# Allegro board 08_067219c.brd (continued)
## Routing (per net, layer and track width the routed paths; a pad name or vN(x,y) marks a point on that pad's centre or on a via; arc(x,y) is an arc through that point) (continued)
ADP2360_PG: length 65.4
  TOP w0.203: U8.2 10.47,17.58 v1(9.91,17.02) R29.1 ; R15.1 v1(29.08,58.17)
  BOTTOM w0.203: v1(29.08,58.17) 29.62,58.7 29.62,60.81 28.83,61.59 19.68,61.59 18.54,60.45 18.54,41.91 13.72,37.08 12.95,37.08 12.21,36.34 12.21,24.27 9.4,21.46 9.4,17.53 v1(9.91,17.02)
ADR1/SPISSO: length 72.7
  TOP w0.178: R82.2 v1(66.55,47.68) ; R128.1 R31.2 P14.1 28.05,50.93 33.53,50.93 v1(33.78,51.18) R13.2
  BOTTOM w0.178: v1(66.55,47.68) 66.55,48.51 64.26,50.8 64.26,62.68 62.28,64.66 36.14,64.66 35.56,64.07 35.56,52.07 34.67,51.18 v1(33.78,51.18)
ADR2/IO2/MCLK: length 134.9
  TOP w0.178: P17.1 R34.1 R32.2 ; v1(50.8,111.76) 51.07,112.03 A2.1 ; v1(44.58,84.68) 44.58,84.69 44.24,85.03 U10.32 ; v1(36.07,50.5) 37.13,50.5 37.31,50.32 U7.23
  TOP w0.508: R70.2 v1(47.19,63.94)
  L3_PWR w0.178: P17.1 24.77,49.02 22.99,50.8 20.2,50.8 18.58,52.42 18.58,63.92 37.21,82.55 42.45,82.55 v1(44.58,84.68) 45,85.1 45,88.65 41.55,92.1 41.55,96.8 41.91,97.16 41.91,105.28 48.39,111.76 v1(50.8,111.76)
  BOTTOM w0.178: 36.07,50.5 33.45,50.5 33.02,50.93 28.07,50.93 P17.1 ; 36.07,50.5 v1(36.07,50.5) ; 36.07,50.5 36.07,51.28 35.94,51.4 35.94,62.74 36.77,63.57 45.03,63.57 45.4,63.94 v1(47.19,63.94)
BD28623_BCLK: length 2.5
  TOP w0.178: R119.1 52.07,108.24 51.81,107.98 R127.2
BD28623_MUTEX: length 94.1
  TOP w0.203: A2.7 54.4,113.24 54.69,112.95 54.69,111.81 55.21,111.29 55.21,109.38 56.26,108.33 v1(56.26,108.31) 56.67,108.31 57.15,107.83 R42.2
  BOTTOM w0.203: v1(56.26,108.31) 58.67,105.89 58.67,96.9 57.4,95.63 55.5,95.63 54.48,94.61 39.24,94.61 38.86,94.23 38.86,92.2 39.24,91.82 40.95,91.82 42.89,89.89 44.09,89.89 46,87.99 46,84.36 44.93,83.29 44.93,77.83 41.66,74.55 38.35,74.55 37.34,75.56 30.35,75.56 23.88,69.09 P23.3
BD28623_SDATA_IN: length 79
  TOP w0.178: R11.1 v1(39.76,61.7) ; R118.1 v1(50.93,108.97) ; R75.2 v1(57.35,63.32)
  L3_PWR w0.178: v1(50.93,108.97) 52.07,110.11 56.13,110.11 57.87,108.37 57.87,106.34 58.42,105.79 58.42,98.16 57.4,97.14 57.4,72.01 57.87,71.54 57.87,71.53 58.67,70.73 58.67,64.65 v1(57.35,63.32) 55.77,64.9 49.4,64.9 47.62,63.12 43.81,63.12 43.48,62.79 43.48,62.03 42.8,61.34 41.15,61.34 40.79,61.7 v1(39.76,61.7)
  BOTTOM w0.178: v1(39.76,61.7) 39.77,61.71 C5.2
LT3502_FB: length 3
  TOP w0.203: U2.3 14.32,40.67 15.11,39.89 R2.2
  TOP w0.254: R2.2 14.87,39.52 R3.2
MP1: length 53.4
  TOP w0.203: v1(46.48,76.2) 46.74,76.46 U10.10 ; v1(64.2,70.93) R129.1 U9.1
  BOTTOM w0.203: P5.1 43.05,90.3 44.32,90.3 46.48,88.14 46.48,83.19 48.03,81.64 48.03,79.34 47.15,78.46 47.09,78.46 46.48,77.85 v1(46.48,76.2) 46.48,75.19 48.42,73.25 54.33,73.25 57.43,76.35 64.62,76.35 65.66,75.31 65.66,72.39 v1(64.2,70.93)
MP2: length 8.5
  TOP w0.254: P5.3 44.32,91.57 44.32,90.8 45.74,89.39 U10.29
MP3: length 7.7
  TOP w0.254: U10.28 46.24,89.65 45.22,90.67 P5.5
MP7: length 18.6
  TOP w0.203: v1(51.69,79.76) 50.42,79.76 50.19,79.53 U10.14
  BOTTOM w0.203: v1(51.69,79.76) 52.83,80.9 52.83,88.14 P5.7
MP8: length 8.7
  TOP w0.254: U10.27 46.74,89.65 P5.9
MP9: length 10.5
  TOP w0.254: U10.26 47.24,89.15 49.66,91.57 51.2,91.57 P5.11
PDM_CLK: length 86.8
  TOP w0.178: v1(52.28,63.32) 52.27,63.34 R72.2
  TOP w0.203: R52.2 v1(48.07,27.78)
  L3_PWR w0.178: v1(52.28,63.32) 50.3,61.34 43.69,61.34 43.05,60.71 40.51,60.71 40.07,60.26 37.02,60.26 34.67,57.91 30.48,57.91 29.97,57.4 29.07,57.4 28.81,57.66 P16.2
  BOTTOM w0.178: P16.2 27.56,56.52 26.8,55.75 25.4,55.75 23.62,53.98 23.62,48.77 22.99,48.13 22.99,47.5 23.38,47.1 29.86,47.1 31.37,45.59 31.37,42.43 31.89,41.91 36.96,41.91 37.21,41.66 37.21,40.39 39.12,38.48 40.01,38.48 41.95,36.54 43.4,36.54 45.59,38.73 47.62,38.73 48.89,37.46 48.89,30.35 48.07,29.53 v1(48.07,27.78)
PDM_DATA0: length 65.2
  TOP w0.178: R53.2 v1(40,37.72) ; v1(46.51,26.03) C67.2 45.71,26.03 R56.2
  BOTTOM w0.178: P4.1 21.53,58.93 25.1,58.93 25.27,58.75 25.27,56.77 24.89,56.39 23.49,56.39 21.46,54.36 21.46,46.89 24.03,44.32 27.69,44.32 28.33,44.97 30.09,44.97 30.35,44.7 30.35,41.94 32.28,40 37.05,40 39.34,37.72 v1(40,37.72) 41.66,36.06 41.66,25.65 42.3,25.01 45.49,25.01 v1(46.51,26.03)
PDM_DATA1: length 121.3
  TOP w0.178: v1(59.06,44.58) R54.2 C66.2 ; R74.2 v1(54.81,63.32) ; R55.2 v1(29.71,44.45)
  L3_PWR w0.178: P23.1 23.88,56.07 25.17,54.78 30.01,54.78 31.8,56.57 34.21,56.57 37.07,59.42 42.66,59.42 43.92,60.68 50.77,60.68 53.42,63.32 v1(54.81,63.32)
  BOTTOM w0.178: P23.1 20.95,54.74 20.95,46.74 23.75,43.94 28.07,43.94 28.58,44.45 v1(29.71,44.45) 29.71,41.79 31.88,39.62 36.7,39.62 39.12,37.21 39.75,37.21 41.16,35.8 41.16,25.51 42.05,24.63 47.36,24.63 50.15,27.42 50.53,27.42 50.8,27.69 50.8,31.5 56.77,37.46 56.77,39.12 59.06,41.41 v1(59.06,44.58)
SPI_EEPROM_CS: length 8
  TOP w0.178: R71.2 v1(49.73,63.74)
  TOP w0.508: R8.1 v1(44.07,62.23)
  L3_PWR w0.178: v1(44.07,62.23) 44.45,61.85 47.84,61.85 v1(49.73,63.74)
UNNAMED_2_AD243XW_I5_ACM: length 7.5
  TOP w0.254: U7.27 v1(42.7,49.78)
  BOTTOM w0.508: C86.2 41.91,44.7 41.91,45.97 42.7,46.76 v1(42.7,49.78) C85.2
UNNAMED_2_AD243XW_I5_BCLK: length 26.4
  TOP w0.178: R10.2 41.78,59.05 42.04,58.8 v1(42.67,58.8) 43.39,58.09 43.39,57.35 43.2,57.16 U7.9
  L3_PWR w0.178: v1(42.67,58.8) 43.26,59.39 47.19,59.39 47.65,59.84 52.73,59.84 55.12,62.23 58.67,62.23 59.82,61.09 P11.1
UNNAMED_2_AD243XW_I5_BCM: length 7.5
  TOP w0.254: U7.35 v1(46.7,49.78)
  BOTTOM w0.508: C43.2 47.62,44.58 47.62,45.34 46.33,46.64 C89.2 46.33,49.41 v1(46.7,49.78)
UNNAMED_2_AD243XW_I5_DVDD1: length 24.2
  TOP w0.254: U7.3 46.22,56.03 46.22,56.51 46.33,56.62 v1(46.33,56.92) 46.7,56.55 U7.2
  TOP w0.508: v1(46.33,57.38) v1(46.33,56.92)
  BOTTOM w0.254: R4.1 47,61.56 47.34,61.9 56.38,61.9 56.63,61.65 56.63,60.21 56.91,59.93 60.08,59.93 P9.1
  BOTTOM w0.508: R4.1 47,61.04 46.2,60.24 C2.1 C4.2 46.2,57.51 v1(46.33,57.38) v1(46.33,56.92)
UNNAMED_2_AD243XW_I5_GPIO7: length 12.3
  TOP w0.178: U7.14 38.91,54.82 37.34,56.39 37.34,57.66 36.83,58.17 R15.2
UNNAMED_2_AD243XW_I5_IRQ: length 5.6
  TOP w0.178: U7.24 35.46,49.82 R14.1
UNNAMED_2_AD243XW_I5_ISENSEN: length 13.3
  TOP w0.254: 53.47,50.67 52.58,50.67 52.02,50.12 48.64,50.12 48.38,49.86 48.34,49.82 U7.37 ; 53.47,50.67 R100.2 ; 53.47,50.67 53.47,49.91 53.15,49.59 48.63,49.59 48.16,49.12 U7.36
UNNAMED_2_AD243XW_I5_MISO: length 6.2
  TOP w0.178: R21.1 36.19,54.86 37.74,53.32 U7.17
UNNAMED_2_AD243XW_I5_MOSI: length 5.9
  TOP w0.178: U7.18 37.48,52.82 36.58,53.72 R22.1
UNNAMED_2_AD243XW_I5_PLVDD: length 10.2
  TOP w0.254: U7.48 48.39,55.32 48.64,55.06 v1(48.64,54.79) 48.62,54.82 U7.47
  BOTTOM w0.508: C10.2 53.36,55.25 52.7,54.6 C7.1 C9.2 C11.1 48.83,54.6 v1(48.64,54.79) ; P6.1 54.74,58.67
UNNAMED_2_AD243XW_I5_SCK: length 5.7
  TOP w0.178: U7.19 36.96,52.32 36.7,52.58 R23.1
UNNAMED_2_AD243XW_I5_SCL: length 6.5
  TOP w0.178: U7.16 37.88,53.82 35.94,55.75 35.68,55.75 R20.1
UNNAMED_2_AD243XW_I5_SDA: length 7.2
  TOP w0.178: U7.15 38.52,54.32 36.58,56.26 36.58,57.04 36.37,57.24 R19.1
UNNAMED_2_AD243XW_I5_SIO0: length 5.2
  TOP w0.203: R6.2 46.34,59.17 45.17,58 45.17,57.97 45.11,57.91 45.11,56.82 45.2,56.74 U7.5
UNNAMED_2_AD243XW_I5_SIO1: length 4.9
  TOP w0.203: U7.6 44.7,60.2 R7.2
UNNAMED_2_AD243XW_I5_SIO3: length 5.1
  TOP w0.178: U7.12 41.7,58.12 40.64,59.18 R11.2
UNNAMED_2_AD243XW_I5_SIO4: length 8
  TOP w0.178: U7.13 39.17,55.32 37.85,56.64 37.85,58.29 37.21,58.93 R12.2
UNNAMED_2_AD243XW_I5_SWN: length 6.1
  TOP w0.254: R101.2 52.47,51.82 51.31,50.66 48.63,50.66 48.48,50.82 U7.39
UNNAMED_2_AD243XW_I5_SYNC: length 28.6
  TOP w0.178: R9.2 42.93,60.1 43.72,59.31 v1(43.72,58.8) 43.77,58.75 43.77,57.19 43.7,57.12 U7.8
  L3_PWR w0.178: v1(43.72,58.8) 47.62,58.8 48.26,59.44 55.88,59.44 56.39,59.94 62.23,59.94 62.86,59.31 62.86,57.78 P12.1
UNNAMED_2_AD243XW_I5_TRXVDD: length 6.8
  TOP w0.254: 44.7,48.51 U7.31
  TOP w0.508: 54.24,53.09 R33.2
  TOP w0.635: P10.1 57.02,53.09 v1(56.64,53.09) v1(56.13,53.09) v1(55.63,53.09) v1(55.12,53.09) 54.24,53.09
  L4_PWR w0.508: 56.6,53.85 P10.1 57.78,52.67
  vias: v1(44.3,44.19) v1(44.71,45.33) v1(44.68,44.57) v1(44.68,43.74) v1(45.06,44.19)
UNNAMED_2_CAP_I160_N1: length 4.1
  TOP w0.508: E10.1 C79.1 P1.1
UNNAMED_2_CN3P_I189_N2: length 28.3
  TOP w0.203: R6.1 46.34,62.37 45.5,63.21 37.55,63.21 36.45,62.1 26.42,62.1 25.65,61.34 21.41,61.34 P4.2
UNNAMED_2_CN3P_I190_N2: length 23.2
  TOP w0.203: R7.1 45.21,62.36 44.77,62.8 37.78,62.8 36.68,61.7 26.64,61.7 25.88,60.93 24.61,60.93 P23.2
UNNAMED_2_CN24PODDEVEN_I191_N2: length 2.1
  TOP w0.203: P1.3 R66.1
UNNAMED_2_CN24PODDEVEN_I191_N3: length 2.1
  TOP w0.203: P1.5 R67.1
UNNAMED_2_CN24PODDEVEN_I191_N4: length 2.1
  TOP w0.203: P1.7 R68.1
UNNAMED_2_CN24PODDEVEN_I191_N5: length 2.1
  TOP w0.203: P1.9 R69.1
UNNAMED_2_CN24PODDEVEN_I191_N6: length 2.1
  TOP w0.203: P1.11 R70.1
UNNAMED_2_CN24PODDEVEN_I191_N7: length 2.1
  TOP w0.203: P1.13 R71.1
UNNAMED_2_CN24PODDEVEN_I191_N8: length 2.1
  TOP w0.203: P1.15 R72.1
UNNAMED_2_CN24PODDEVEN_I191_N9: length 2.1
  TOP w0.203: P1.17 R74.1
UNNAMED_2_CN24PODDEVEN_I191_N10: length 2.1
  TOP w0.203: P1.19 R75.1
UNNAMED_2_CN24PODDEVEN_I191_N11: length 2.1
  TOP w0.203: P1.21 R76.1
UNNAMED_2_DIOLED_I111_N: length 1.8
  TOP w0.203: DS2.C R35.2
UNNAMED_2_DIOLED_I114_N: length 1.8
  TOP w0.203: DS3.C R36.2
UNNAMED_5_ADLT3502_I61_BD: length 14.8
  TOP w0.203: R2.1 13.87,39.98 U2.2
  TOP w0.508: R2.1 v1(14.1,39.06)
  BOTTOM w0.508: v1(14.1,39.06) 13.21,39.96 13.21,48.26 12.32,49.15 v1(10.49,49.15)
UNNAMED_5_ADLT3502_I61_BOOST: length 1.5
  TOP w0.203: 13.87,43.75 U2.7
  TOP w0.508: C28.2 13.87,43.75
UNNAMED_5_ADLT3502_I61_DA: length 0.9
  TOP w0.203: 14.61,43.69 14.32,43.41 U2.6
UNNAMED_5_ADLT3502_I61_SHDNN: length 3.3
  TOP w0.203: U2.4 14.77,40.85 14.99,40.64 R1.1 16.26,42.03 R48.2
UNNAMED_5_ADP2360_I29_EN: length 2.4
  TOP w0.203: R24.1 8.76,17.02 9.14,17.4 9.4,17.4 9.82,17.82 U8.1
UNNAMED_5_ADP2360_I29_FB: length 4.6
  TOP w0.203: C37.1 13.55,17.48 R40.1 13.54,16.25 R41.2 11.77,16.8 U8.4
UNNAMED_5_ADP2360_I29_ITH: length 1.8
  TOP w0.203: U8.3 R27.2
UNNAMED_5_ADP2360_I29_SS: length 1.6
  TOP w0.203: U8.5 C27.2
UNNAMED_5_ADP2360_I29_SW: length 4.6
  TOP w0.381: L6.1 10.92,25.16 10.92,22.48 10.47,22.03 U8.7
UNNAMED_5_CAP_I36_N2: length 11.2
  TOP w0.203: v1(15.88,17.65) 14.72,17.65 C37.2 14.55,17.48 R40.2
  BOTTOM w0.203: v1(17.91,25.4) 15.88,23.37 v1(15.88,17.65)
UNNAMED_5_CAP_I38_N2: length 3.1
  TOP w0.508: R47.2 16.02,29.98 D1.A
UNNAMED_5_DIOLED_I72_P: length 2.1
  TOP w0.508: DS1.A R16.1
UNNAMED_5_DIOLED_I78_P: length 1.6
  TOP w0.508: R47.1 DS5.A
UNNAMED_6_ADA46612V4_I99_: length 12.2
  TOP w0.203: C77.2 19.44,93.46 U13.7 ; C77.2 20.35,93.08 20.72,92.71 20.72,89.92 19.82,89.02 C82.P ; C77.2 19.15,93.08 18.94,93.28 U13.6
UNNAMED_6_ADA46612V4_I99__1: length 2.4
  TOP w0.203: U13.5 18.44,93.87 18.31,93.74 C75.1 R92.2
UNNAMED_6_ADA46612V4_I100_: length 13.3
  TOP w0.203: U13.2 19.44,98.42 19.96,98.94 C76.2 ; C76.2 20.46,98.42 19.94,97.9 U13.1 ; C76.2 21.1,98.94 21.35,99.19 21.35,102.62 20.72,103.25 C81.P
UNNAMED_6_ADA46612V4_I100__1: length 2.6
  TOP w0.203: R91.2 18.93,99.07 C74.1 U13.3
UNNAMED_6_CAP_I60_N1: length 10.9
  TOP w0.203: R94.2 R96.1 7.36,89.02 C84.1 7.36,92.81 8.12,93.57 P20.2
UNNAMED_6_CAP_I64_N1: length 5.1
  TOP w0.203: C77.1 19.83,91.39 19.62,91.19 17.52,91.19 17.31,91.39 R92.1 R90.2
UNNAMED_6_CAP_I67_N1: length 5.3
  TOP w0.203: R89.2 R91.1 17.93,100.85 18.18,101.09 20.21,101.09 20.46,100.84 C76.1
UNNAMED_6_CAP_I74_N1: length 6.4
  TOP w0.203: P20.3 4.4,101.29 6.36,103.25 R95.1 C83.1 R93.2
UNNAMED_6_CAP_I86_N1: length 8.8
  TOP w0.203: E2.2 C55.1 11.29,125.19 12.33,126.24 12.33,127.51 13.58,128.75 C57.P
UNNAMED_6_CAP_I91_N1: length 7.6
  TOP w0.203: C58.P 12.08,112.52 11.2,113.4 C56.1 E3.2
UNNAMED_6_CAPP_I68_N2: length 2.2
  TOP w0.203: R94.1 C82.N
UNNAMED_6_CAPP_I69_N2: length 2.2
  TOP w0.203: R93.1 C81.N
UNNAMED_6_CAPP_I103_N2: length 3.1
  TOP w0.203: C57.N 22.76,128.75 23.44,128.07 R73.1
UNNAMED_6_CAPP_I104_N2: length 3.2
  TOP w0.203: C58.N 22.86,112.52 23.44,113.11 R84.1
UNNAMED_6_CN3P_I18_N2: length 2.9
  TOP w0.203: P7.2 9.86,116.94 E3.1
UNNAMED_6_CN3P_I18_N3: length 2.9
  TOP w0.203: E2.1 5.26,125.19 P7.3
UNNAMED_15_CAP_I9_N2: length 3.2
  TOP w0.241: L2.2 33.9,33.18 33.66,32.94 33.66,32.21 C30.2 33.66,31.74 33.66,30.88 FL1.1
UNNAMED_15_CAP_I13_N1: length 3.2
  TOP w0.241: FL1.2 33.26,30.88 33.26,31.74 C29.1 33.26,32.21 33.26,32.94 33.02,33.18 L1.2
UNNAMED_15_CAP_I18_N1: length 19.5
  TOP w0.508: v1(40.13,24.76) C31.1 R38.2 ; v1(26.8,24.76) C32.1 R37.2
  BOTTOM w0.508: v1(40.13,24.76) 39.11,25.78 27.82,25.78 v1(26.8,24.76)
UNNAMED_15_CAP_I95_N1: length 6.9
  TOP w0.241: C33.1 33.26,22.91 33.26,23.25 32.26,24.25 R37.1 32.26,25.27 33.26,26.27 33.26,27.23 FL1.3
UNNAMED_15_CAP_I95_N2: length 27.3
  TOP w0.241: P27.4 32.64,8.13 33.26,8.75 33.26,19.13 C33.2
  BOTTOM w0.381: L3.1 24.13,4.3 28.97,4.3 29.85,3.43 31.52,3.43 P27.4
UNNAMED_15_CAP_I96_N1: length 6.9
  TOP w0.241: FL1.4 33.66,27.23 33.66,26.27 34.66,25.27 R38.1 34.66,24.25 33.66,23.25 33.66,22.91 C34.1
UNNAMED_15_CAP_I96_N2: length 17.2
  TOP w0.241: C34.2 33.66,19.13 P27.5
  BOTTOM w0.889: P27.5 33.66,9.37 L4.1
UNNAMED_15_DIOSCHOTTKY_I87_P: length 6.9
  BOTTOM w0.508: L4.2 30.81,9.37 29.24,10.95 27.49,10.95 P27.9
UNNAMED_15_MODRJE7318800XXX_I126_LED1C: length 2.4
  BOTTOM w1.016: R140.1 40.11,9.66 P27.12
UNNAMED_15_MODRJE7318800XXX_I126_LED2C: length 4.6
  BOTTOM w0.508: P27.10 26.82,7.74 R141.2
UNNAMED_16_CAP_I13_N1: length 3.2
  TOP w0.241: FL2.1 56.14,30.88 56.14,31.74 C44.1 56.14,32.21 56.14,32.94 56.38,33.18 L11.2
UNNAMED_16_CAP_I15_N2: length 3.2
  TOP w0.241: L10.2 55.49,33.18 55.74,32.94 55.74,32.21 C48.2 55.74,31.74 55.74,30.88 FL2.2
UNNAMED_16_CAP_I17_N1: length 19.4
  TOP w0.508: v1(49.28,24.76) C93.2 R103.1 ; v1(62.61,24.76) C94.1 R104.1
  BOTTOM w0.508: v1(62.61,24.76) 61.71,25.65 50.17,25.65 v1(49.28,24.76)
UNNAMED_16_CAP_I25_N1: length 6.6
  L3_PWR w0.508: P21.7 58.18,7.38 ; 60.1,8.44 P21.11 61.26,9.6 ; P21.3 54.1,7.38
  L3_PWR w0.635: P21.3 53.08,5.31 P21.2
  vias: v1(65.41,11.43) v1(65.41,10.92) v1(65.41,10.41) v1(66.04,11.43) v1(66.04,10.92) v1(66.04,10.41) v1(66.67,11.43) v1(66.67,10.92) v1(66.67,10.41) v1(67.31,11.43) v1(67.31,10.92) v1(67.31,10.41)
UNNAMED_16_CAP_I25_N2: length 3.5
  BOTTOM w0.406: R98.2 Q1.4 C50.2
UNNAMED_16_CAP_I58_N2: length 1.9
  BOTTOM w0.635: R45.1 66.71,4.83 C46.2
UNNAMED_16_CAP_I69_N1: length 6.9
  TOP w0.241: FL2.3 55.74,27.23 55.74,26.27 54.74,25.27 R103.2 54.74,24.25 55.74,23.25 55.74,22.91 C95.1
UNNAMED_16_CAP_I69_N2: length 27.3
  TOP w0.241: P21.4 55.12,8.33 55.74,8.94 55.74,19.13 C95.2
  BOTTOM w0.381: L12.1 46.61,4.3 51.45,4.3 52.32,3.43 54,3.43 P21.4
UNNAMED_16_CAP_I70_N1: length 6.9
  TOP w0.241: FL2.4 56.14,27.23 56.14,26.27 57.14,25.27 R104.2 57.14,24.25 56.14,23.25 56.14,22.91 C61.1
UNNAMED_16_CAP_I70_N2: length 17.2
  TOP w0.241: C61.2 56.14,19.13 P21.5
  BOTTOM w0.508: L13.1 P21.5
UNNAMED_16_MODRJE7318800XXX_I93_LED1C: length 4.4
  BOTTOM w0.508: P21.12 61.24,11.01 R143.1
UNNAMED_16_MODRJE7318800XXX_I93_LED2A: length 6.4
  BOTTOM w0.508: P21.9 50.07,11.05 51.56,11.05 53.24,9.37 R142.2
UNNAMED_17_CAP_I107_N1: length 6.8
  TOP w0.203: R26.2 v1(85.46,83.5) ; R97.2 v1(85.46,78.3)
  TOP w0.508: R17.2 v1(80.9,75.82) ; v1(72.39,78.99) E17.2 C51.1 A3.8
UNNAMED_17_CAP_I108_N1: length 16.9
  TOP w0.508: v1(42.55,38.99) 41.66,38.99 C62.1 ; C64.1 v1(32.25,45.73) ; v1(56.52,47.12) C63.1 v1(59.31,47.12) ; 63.96,39 E4.2 ; E4.2 63.24,39.75 ; E4.2 63.96,40.5 ; C65.1 v1(42.57,28.46)
  BOTTOM w0.305: v1(42.55,38.99) 42.55,39.5 43.01,39.97 v1(43.6,39.97)
  BOTTOM w0.508: v1(53.6,45.74) v1(55.3,45.74) 56.52,46.96 v1(56.52,47.12) ; v1(32.25,45.73) 33.59,45.73 v1(33.6,45.74) ; v1(45.3,28.42) v1(43.6,28.42) 42.61,28.42 v1(42.57,28.46)
  vias: v1(62.1,40.51) v1(62.1,40) v1(62.1,39.5) v1(62.1,38.99) v1(62.61,40.51) v1(62.61,40) v1(62.61,39.5) v1(62.61,38.99)
UNNAMED_17_CAP_I156_N1: length 3.6
  TOP w0.508: A1.8 74.81,86.49 C69.1 74.8,86.49 E9.2
UNNAMED_17_ICIM69D120_I169_DATA: length 4.1
  TOP w0.203: R54.1 v1(56.51,44.58)
  BOTTOM w0.203: v1(56.51,44.58) 56.26,44.32 54.32,44.32 v1(53.6,45.04)
UNNAMED_17_ICIM69D120_I170_CLOCK: length 53.6
  TOP w0.203: v1(48.77,28.78) R52.1
  BOTTOM w0.203: 49.4,35.05 49.4,30.23 48.77,29.59 v1(48.77,28.78) 48.77,27.56 48.26,27.05 45.97,27.05 v1(45.3,27.72) ; 49.4,35.05 49.4,37.59 47.73,39.27 v1(45.3,39.27) 43.12,37.08 42.04,37.08 40.13,38.99 39.37,38.99 37.6,40.75 37.6,41.82 36.83,42.59 36.83,44.45 36.24,45.04 v1(35.3,45.04) ; 49.4,35.05 52.83,35.05 55.94,38.16 55.94,40.82 57.23,42.12 57.23,44.75 56.79,45.19 56.27,45.19 56.12,45.04 v1(55.3,45.04)
UNNAMED_17_ICIM69D120_I170_DATA: length 2.4
  TOP w0.203: R55.1 v1(32.26,44.45)
  BOTTOM w0.203: v1(33.6,45.04) 32.85,45.04 v1(32.26,44.45)
UNNAMED_17_ICIM69D120_I171_DATA: length 2.7
  TOP w0.203: R56.1 v1(42.92,26.03)
  BOTTOM w0.203: v1(43.6,27.72) 42.92,27.04 v1(42.92,26.03)
UNNAMED_17_ICIM69D120_I172_DATA: length 2.8
  TOP w0.203: R53.1 v1(42.55,37.72)
  BOTTOM w0.203: v1(42.55,37.72) 43.6,38.77 v1(43.6,39.27)
UNNAMED_17_ICM24512_I103_E0: length 2.6
  TOP w0.203: A3.1 R131.2 R17.1
UNNAMED_17_ICM24512_I103_E1: length 3.6
  TOP w0.203: A3.2 R130.2 R97.1
UNNAMED_17_ICM24512_I103_E2: length 3.6
  TOP w0.203: R26.1 R28.2 A3.3
UNNAMED_17_ICM24512_I103_SCL: length 2
  TOP w0.203: A3.6 R25.1
UNNAMED_17_ICM24512_I103_SDA: length 2
  TOP w0.203: A3.5 R30.1
UNNAMED_17_ICM24512_I159_SCL: length 2
  TOP w0.203: A1.6 R61.1
UNNAMED_17_ICM24512_I159_SDA: length 2
  TOP w0.203: A1.5 R62.1
UNNAMED_18_7404V6_I276_Y: length 1.6
  TOP w0.203: U15.4 R135.1
UNNAMED_18_ADAU1701_I166_ADCRES: length 1.7
  TOP w0.203: U10.3 43.24,76.14 R109.2
UNNAMED_18_ADAU1701_I166_CM: length 2.9
  TOP w0.254: U10.40 39.39,83.03 C102.1 C104.1
UNNAMED_18_ADAU1701_I166_DVDD: length 4.8
  TOP w0.203: C109.1 50.61,84.53 U10.24 ; U10.13 C107.1
  TOP w0.508: C107.1 v1(51.55,79.03) ; C109.1 v1(51.55,84.72)
  vias: v1(51.18,75.3) v1(51.18,74.79) v1(51.18,74.28) v1(51.69,75.3) v1(51.69,74.79) v1(51.69,74.28) v1(54.86,83.44) v1(55.37,83.44)
UNNAMED_18_ADAU1701_I166_FILTA: length 2.8
  TOP w0.254: U10.47 C98.1 C100.1
UNNAMED_18_ADAU1701_I166_FILTD: length 2.9
  TOP w0.254: U10.41 39.36,82.53 C113.1 C111.1
UNNAMED_18_ADAU1701_I166_MP6: length 3.7
  TOP w0.203: U10.15 50.06,80.03 50.42,80.39 52.21,80.39 R110.2
UNNAMED_18_ADAU1701_I166_PLLLF: length 4.8
  TOP w0.203: U10.35 C110.1 C108.1
UNNAMED_18_ADAU1701_I166_RESETB: length 4.3
  TOP w0.203: U10.5 44.24,76.75 44.07,76.58 44.07,75.17 44.41,74.83 C78.2 44.46,74.76 R44.1
UNNAMED_18_ADAU1701_I166_VDRIVE: length 5.4
  TOP w0.254: Q2.1 53.19,81.03 R112.1 U10.17
UNNAMED_18_CAP_I169_N2: length 1
  TOP w0.203: R111.1 C108.2
UNNAMED_18_CAP_I344_N1: length 3.1
  BOTTOM w0.508: R51.1 C80.1 P2.2
UNNAMED_18_CN2P_I318_N1: length 2.3
  TOP w0.203: R113.1 P22.1
UNNAMED_18_CN10P_I337_N1: length 4.1
  TOP w0.178: P2.1 R77.1
UNNAMED_18_CN10P_I337_N3: length 4.1
  TOP w0.178: P2.3 R78.1
UNNAMED_18_CN10P_I337_N4: length 8.1
  TOP w0.178: P2.4 R117.1 79.38,54.79 79.56,54.61 P44.1
UNNAMED_18_CN10P_I337_N5: length 4.1
  TOP w0.178: P2.5 R79.1
UNNAMED_18_CN10P_I337_N6: length 8.3
  TOP w0.178: P43.1 79.56,51.94 79.38,52.12 R125.1 P2.6
UNNAMED_18_CN10P_I337_N7: length 4.1
  TOP w0.178: P2.7 R80.1
UNNAMED_18_CN10P_I337_N8: length 4.4
  TOP w0.178: R81.1 P2.8
UNNAMED_18_CN10P_I337_N9: length 4.1
  TOP w0.178: P2.9 R82.1
UNNAMED_18_DIOLED_I280_P: length 2
  TOP w0.203: DS4.A 71.42,65.2 R135.2
UNNAMED_19_CAP_I7_N1: length 1.3
  TOP w0.508: C123.1 R124.2
UNNAMED_19_CAP_I17_N1: length 10.6
  TOP w0.254: C115.1 57.66,110.61 R124.1 61.09,109.34 L17.1 ; A2.8 54.85,113.74 55.05,113.54
  TOP w0.508: 55.05,113.54 55.24,113.34 55.24,112.27 56.52,110.99 C115.1
UNNAMED_19_CAP_I17_N2: length 3.2
  TOP w0.203: 55.37,114.22 55.36,114.24 A2.9
  TOP w0.508: 55.37,114.22 56.91,114.22 C115.2
UNNAMED_19_CAP_I20_N2: length 3.2
  TOP w0.254: A2.12 54.99,115.74
  TOP w0.508: 54.99,115.74 56.97,115.74 C118.2
UNNAMED_19_CAP_I21_N1: length 1.4
  TOP w0.508: R123.2 C122.1
UNNAMED_19_CAP_I26_N1: length 2.7
  TOP w0.203: A2.22 49.29,114.24 49.28,114.22
  TOP w0.508: 49.28,114.22 47.87,114.22 C114.1
UNNAMED_19_CAP_I26_N2: length 6.3
  TOP w0.254: A2.23 49.86,113.74 49.66,113.54
  TOP w0.508: 49.66,113.54 49.02,112.9 49.02,112.01 48.12,111.11 C114.2
  TOP w0.635: C114.2 45.97,111.11 C119.2
UNNAMED_19_CAP_I28_N2: length 2.7
  TOP w0.254: 49.4,115.74 A2.19
  TOP w0.508: C121.2 47.86,115.74 49.4,115.74
UNNAMED_19_CAP_I32_N2: length 11.4
  TOP w1.016: L17.2 C129.2 P48.1
UNNAMED_19_CAP_I33_N1: length 11.4
  TOP w1.016: P47.1 C128.1 L16.2
UNNAMED_19_CAP_I38_N2: length 11.4
  TOP w1.016: L15.2 C127.2 P46.1
UNNAMED_19_CAP_I40_N1: length 1.5
  TOP w0.508: R122.2 C120.1
UNNAMED_19_CAP_I42_N1: length 1.4
  TOP w0.508: R121.2 C119.1
UNNAMED_19_CAP_I44_N1: length 11.4
  TOP w1.016: L14.2 C126.1 P45.1
UNNAMED_19_CAP_I49_N1: length 4.4
  TOP w0.254: A2.16 52.07,119.48 52.96,120.37 C130.1
UNNAMED_19_CAP_I51_N1: length 6.8
  TOP w0.203: C90.1 R116.1 55.12,108.33 54.5,108.95 54.5,111.31 53.57,112.23 A2.6
UNNAMED_19_CAP_I55_N1: length 5
  TOP w0.254: C124.1 51.18,120.78 51.57,120.38 A2.17
UNNAMED_19_DIOLED_I16_N: length 6.5
  TOP w0.203: DS6.C 48.64,108.84 49.91,110.11 49.91,112.9 50.25,113.24 A2.24
UNNAMED_19_DIOLED_I16_P: length 1.6
  TOP w0.203: DS6.A R115.2
UNNAMED_19_ICBD28623MUV_I18_BCLK: length 1.9
  TOP w0.203: R119.2 A2.3
UNNAMED_19_ICBD28623MUV_I18_GAIN: length 6.7
  TOP w0.203: A2.5 53.07,111.98 53.98,111.08 R114.2 R83.1
UNNAMED_19_ICBD28623MUV_I18_LRCLK: length 2.1
  TOP w0.203: R120.2 52.57,111.36 A2.4
UNNAMED_19_ICBD28623MUV_I18_SDATA: length 2.1
  TOP w0.203: R118.2 51.57,111.37 A2.2
USBI_SCL: length 47.4
  TOP w0.203: v1(65.16,88.15) R137.2 U14.4 ; v1(66.55,57.84) R77.2
  BOTTOM w0.203: v1(65.16,88.15) 65.16,88.78 66.04,89.66 70.1,89.66 72.03,87.73 73.81,87.73 74.52,87.02 74.52,82.53 67.79,75.8 67.79,67.23 66.04,65.47 66.04,58.35 v1(66.55,57.84)
USBI_SDA: length 58.6
  TOP w0.203: R78.2 v1(66.55,55.3) ; U12.4 R136.2 v1(65.16,83.57)
  BOTTOM w0.203: v1(65.16,83.57) 65.46,83.57 65.66,83.78 65.66,86.23 64.52,87.38 64.52,89.66 65,90.14 70.26,90.14 72.26,88.14 74.3,88.14 74.93,87.5 74.93,82.36 68.2,75.63 68.2,67.06 66.45,65.31 66.45,58.78 67.69,57.53 67.69,55.75 67.24,55.3 v1(66.55,55.3)
VOUT2: length 46.1
  TOP w0.203: R89.1 v1(15.13,100.2)
  TOP w0.254: v1(43.31,81.66) 43.31,81.41 42.93,81.03 U10.44
  BOTTOM w0.203: v1(15.13,100.2) 18.54,100.2 20.64,98.11 20.64,86.87 24.58,82.93 42.04,82.93 v1(43.31,81.66)
VOUT3: length 37.3
  TOP w0.203: R90.1 v1(14.49,92.08)
  TOP w0.254: v1(42.29,81.66) 42.29,81.66 42.16,81.53 U10.43
  BOTTOM w0.203: v1(42.29,81.66) 41.43,82.52 24.41,82.52 20.19,86.74 20.19,91.69 19.81,92.08 v1(14.49,92.08)

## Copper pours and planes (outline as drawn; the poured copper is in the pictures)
DGND on TOP: 87.63,1.27 1.27,1.27 1.27,138.43 87.63,138.43 ; 22 cut-outs
DGND on BOTTOM: 63.72,14.34 64.88,14.34 65.02,14.48 65.41,14.48 65.53,14.35 65.53,12.45 65.41,12.32 65.02,12.32 64.76,12.59 63.72,12.59
DGND on BOTTOM: 1.27,138.43 87.63,138.43 87.63,1.27 59.62,1.27 59.62,2.28 51.65,2.28 51.65,1.27 37.14,1.27 37.14,2.29 29.17,2.29 29.17,1.27 1.27,1.27 ; 39 cut-outs
DGND on L2_GND, L5_GND: 1.27,138.43 87.63,138.43 87.63,1.27 1.27,1.27 ; 4 cut-outs
DGND on L3_PWR: 42.8,55.44 46.23,55.44 46.23,53.72 46.32,53.5 46.55,53.4 47.31,53.4 47.31,49.28 47.4,49.05 47.62,48.96 56.45,48.96 56.45,45.21 56.54,44.99 56.77,44.89 87.63,44.89 87.63,1.27 81.79,1.27 81.79,18.92 81.7,19.15 81.47,19.24 60.32,19.24 60.1,19.15 60.01,18.92 60.01,9.84 52.26,9.84 52.26,12.45 52.17,12.67 51.94,12.76 36.96,12.76 36.73,12.67 36.64,12.45 36.64,9.84 20.64,9.84 20.64,40.51 29.02,40.51 29.14,40.54 29.24,40.61 32.42,43.78 32.49,43.88 32.51,44.01 32.51,48.51 32.96,48.96 41.27,48.96 41.5,49.05 41.59,49.28 41.59,54.17 42.48,54.17 42.71,54.26 42.8,54.48 ; 1 cut-out
DGND on L3_PWR: 1.27,138.43 87.63,138.43 87.63,86.17 71.82,86.17 71.82,92.33 71.73,92.55 71.5,92.65 65.91,92.65 65.69,92.55 65.6,92.33 65.6,78.55 62.48,78.55 62.26,78.46 62.17,78.23 62.17,64.01 62.26,63.78 62.48,63.69 66.1,63.69 66.1,52.13 61.66,52.13 61.66,58.48 61.57,58.71 61.34,58.8 37.08,58.8 36.86,58.71 36.77,58.48 36.77,56.26 32,56.26 31.88,56.24 31.78,56.17 28.16,52.55 28.09,52.45 28.07,52.32 28.07,47.12 1.27,47.12 ; 16 cut-outs
DGND on L4_PWR: 42.8,55.44 46.23,55.44 46.23,53.72 46.32,53.5 46.55,53.4 47.31,53.4 47.31,49.59 41.59,49.59 41.59,54.17 42.48,54.17 42.71,54.26 42.8,54.48
DGND on L4_PWR: 1.27,138.43 25.08,138.43 25.08,93.92 1.27,93.92 ; 1 cut-out
PGND on TOP, L2_GND, L5_GND: 46.35,4.19 46.35,1.27 51.65,1.27 51.65,2.28 59.62,2.28 59.62,1.27 65.02,1.27 65.02,4.19
PGND on BOTTOM: 46.35,4.19 46.35,1.27 51.65,1.27 51.65,2.28 59.62,2.28 59.62,1.27 65.02,1.27 65.02,4.19 ; 1 cut-out
PGND1 on TOP, BOTTOM, L2_GND, L5_GND: 23.88,4.19 23.88,1.27 29.17,1.27 29.17,2.28 37.14,2.28 37.14,1.27 42.55,1.27 42.55,4.19
VDD_3V3 on TOP: 65.09,40.6 65.09,38.9 65.38,38.61 67.44,38.61 67.69,38.86 67.69,40.64 67.44,40.89 65.38,40.89
VDD_3V3 on TOP: 11.54,53.04 11.54,53.82 12.66,54.93 13.8,54.93 13.8,56.74 7.71,56.74 7.24,56.26 7.24,53.72 7.49,53.47 10.12,53.47 10.55,53.04
VDD_3V3 on TOP: 56.57,80.73 56.57,78.61 56.44,78.49 55.68,78.49 55.55,78.61 55.55,80.73
VDD_3V3 on TOP: 35.81,86.83 39.33,86.83 39.5,87 39.5,88.27 39.33,88.43 35.81,88.43
VDD_3V3 on TOP: 54.62,88.43 51.09,88.43 50.93,88.27 50.93,87 51.09,86.83 54.62,86.83
VDD_3V3 on BOTTOM: 59.51,21.07 59.51,21.64 59.37,21.78 59.37,22.8 59.5,22.92 60.26,22.92 60.39,22.8 60.39,21.78 60.25,21.64 60.25,21.07
VDD_3V3 on L4_PWR: 49.09,107.12 57.98,107.12 57.98,93.09 58.07,92.87 58.29,92.77 64.07,92.77 64.07,84.71 64.16,84.48 64.39,84.39 76.01,84.39 76.01,31.05 69.22,31.05 68.99,30.96 68.9,30.73 68.9,24.32 60.77,24.32 60.54,24.23 60.45,24 60.45,21.53 56.58,21.53 56.58,31.31 63.63,31.31 63.85,31.4 63.94,31.62 63.94,35.5 66.29,35.5 66.52,35.59 66.61,35.81 66.61,48.45 66.52,48.68 66.29,48.77 58.99,48.77 58.99,54.17 66.93,54.17 67.15,54.26 67.25,54.48 67.25,67.31 67.15,67.53 66.93,67.63 61.47,67.63 61.24,67.53 61.15,67.31 61.15,66.36 32.83,66.36 32.6,66.26 32.51,66.04 32.51,62.36 19.56,62.36 19.33,62.26 19.24,62.04 19.24,47.31 1.27,47.31 1.27,93.28 35.43,93.28 35.55,93.31 35.66,93.37 39.88,97.6 48.77,97.6 48.99,97.69 49.09,97.92 ; 1 cut-out
VDD_5V on TOP: 15.53,33.5 15.53,32.3 16.73,32.3 17.53,33.1 17.53,33.15 17.67,33.29 19.61,33.29 19.61,34.58 19.38,34.81 19.38,35.55 15.88,35.55 15.84,35.51 15.84,33.8
VDD_5V on BOTTOM: 61.29,21.07 61.29,21.64 61.15,21.78 61.15,22.8 61.28,22.92 62.04,22.92 62.17,22.8 62.17,21.78 62.03,21.64 62.03,21.07
VDD_5V on BOTTOM: 57.49,8.68 57.49,12.5 57.78,12.8 59.05,12.8 59.44,12.42 59.44,10.89 59.05,10.51 58.67,10.51 58.4,10.24 58.4,8.68
VDD_5V on L4_PWR: 16.45,35.62 37.27,35.62 37.27,26.16 37.37,25.94 37.59,25.84 55.94,25.84 55.94,21.21 56.04,20.98 56.26,20.89 60.77,20.89 60.99,20.98 61.09,21.21 61.09,23.69 68.9,23.69 68.9,10.1 55.94,10.1 55.94,17.27 55.85,17.5 55.63,17.59 29.4,17.59 29.4,22.1 29.31,22.32 29.08,22.42 16.45,22.42
AD243X_IOVDD on TOP: 53.86,56.06 56.44,56.06 56.64,56.26 56.64,57.28 56.52,57.4 55.63,57.4 55.37,57.15 55.37,57.02 55.12,56.77 54.67,56.77 54.6,56.7 53.86,56.7
AD243X_IOVDD on L3_PWR: 66.23,92.01 71.18,92.01 71.18,75.37 67.18,75.37 66.96,75.28 66.87,75.06 66.87,64.33 62.8,64.33 62.8,77.91 65.91,77.91 66.14,78.01 66.23,78.23
AD243X_IOVDD on L4_PWR: 61.79,66.99 66.61,66.99 66.61,54.8 53.78,54.8 53.78,60.71 53.69,60.93 53.47,61.02 46.55,61.02 46.32,60.93 46.23,60.71 46.23,56.07 42.48,56.07 42.26,55.98 42.16,55.75 42.16,54.8 41.27,54.8 41.05,54.71 40.96,54.48 40.96,50.74 38.93,50.74 38.93,53.21 38.83,53.44 38.61,53.53 23.62,53.53 23.4,53.44 23.3,53.21 23.3,47.31 19.88,47.31 19.88,61.72 32.83,61.72 33.05,61.81 33.15,62.04 33.15,65.72 61.47,65.72 61.69,65.82 61.79,66.04
AD243X_ISENSEP on BOTTOM: 65.82,28.96 65.82,26.82 65.35,26.34 64.34,26.34 64.34,25.33 64.5,25.33 64.5,25.02 63.76,25.02 63.76,24.44 64.5,24.44 64.5,22.61 63.76,22.61 63.76,22 64.5,22 64.5,21.82 68.61,21.82 68.61,22 69.35,22 69.35,22.61 68.61,22.61 68.61,24.44 69.35,24.44 69.35,25.02 68.61,25.02 68.61,25.33 68.76,25.33 68.76,26.34 67.49,26.34 67.49,26.36 67.22,26.63 67.22,28.96
AD243X_VBUS on TOP: 12.8,40.18 12.33,39.71 10.53,39.71 10.53,38.49 10.54,38.48 10.54,37.59 10.67,37.46 12.19,37.46 12.33,37.6 12.33,38.57 13.55,39.79 13.55,41.39 12.94,41.39 12.8,41.25
AD243X_VBUS on TOP: 67.08,30.47 67.08,25.98 70.43,25.98 71.25,26.8 71.25,29.72 70.49,30.47
AD243X_VBUS on TOP: 10,20.84 10,22.06 9.82,22.24 9.82,25.87 9.65,26.03 8.13,26.03 8,25.91 8,24.46 8.22,24.24 8.22,21.76 9.13,20.84
AD243X_VBUS on BOTTOM: 68.42,27.17 68.42,28.97 71.09,28.97 71.09,27.17
AD243X_VBUS on BOTTOM: 71.75,17.4 69.68,17.4 69.68,13.12 69.98,12.83 71.37,12.83 71.72,13.17 71.72,14.99 73.41,14.99 73.66,15.24 73.66,16.29 72.87,16.29
AD243X_VBUS on BOTTOM: 45.78,112.39 55.79,112.39 57.06,111.12 59.86,111.12 59.86,122.14 56.48,122.14 51.82,117.47 45.78,117.47
AD243X_VBUS on L3_PWR: 10.48,40.51 20,40.51 20,9.53 20.1,9.3 20.32,9.21 36.96,9.21 37.18,9.3 37.27,9.53 37.27,12.13 51.63,12.13 51.63,4.57 51.72,4.35 51.94,4.25 59.44,4.25 59.66,4.35 59.75,4.57 59.75,6.16 67.95,6.16 68.17,6.25 68.26,6.48 68.26,18.61 81.15,18.61 81.15,1.27 59.62,1.27 59.62,2.29 51.65,2.29 51.65,1.27 37.14,1.27 37.14,2.29 29.17,2.29 29.17,1.27 13.53,1.27 13.53,15.49 13.43,15.72 13.21,15.81 9.33,15.81 9.11,15.72 9.02,15.49 9.02,14.16 7.62,14.16 7.62,26.29 10.16,26.29 10.38,26.38 10.48,26.61
AD243X_VBUS on L4_PWR: 25.72,138.43 87.63,138.43 87.63,1.27 59.62,1.27 59.62,2.29 51.65,2.29 51.65,1.27 37.14,1.27 37.14,2.29 29.17,2.29 29.17,1.27 25.21,1.27 25.21,13.97 25.12,14.19 24.89,14.29 20.83,14.29 20.8,14.29 20.76,14.28 20.73,14.29 20.7,14.29 8.06,14.29 8.06,27.37 10.29,27.37 10.51,27.46 10.6,27.69 10.6,41.34 21.02,41.34 21.02,36.26 16.13,36.26 15.9,36.17 15.81,35.94 15.81,22.1 15.9,21.87 16.13,21.78 28.77,21.78 28.77,17.27 28.86,17.05 29.08,16.95 55.31,16.95 55.31,9.78 55.4,9.55 55.63,9.46 69.22,9.46 69.44,9.55 69.53,9.78 69.53,30.42 76.33,30.42 76.55,30.51 76.64,30.73 76.64,84.71 76.55,84.93 76.33,85.03 64.71,85.03 64.71,93.09 64.61,93.32 64.39,93.41 58.61,93.41 58.61,107.44 58.52,107.67 58.29,107.76 48.77,107.76 48.54,107.67 48.45,107.44 48.45,98.23 39.75,98.23 39.63,98.21 39.53,98.14 35.3,93.92 25.72,93.92 ; 2 cut-outs
AD243X_VIN on TOP: 55.23,58.97 52.74,58.97 52.45,58.67 52.45,57.66 52.74,57.37 55.23,57.37
AD243X_VIN on BOTTOM: 24.61,11.19 23.46,11.19 23.24,11.4 23.24,12.6 23.44,12.8 28.3,12.8 28.3,11.58 25.01,11.58
AD243X_VIN on L4_PWR: 46.86,60.39 53.15,60.39 53.15,44.64 46.16,44.64 46.16,45.97 46.07,46.2 45.85,46.29 42.67,46.29 42.45,46.2 42.35,45.97 42.35,44.51 33.34,44.51 33.34,46.99 33.24,47.21 33.02,47.31 29.97,47.31 29.75,47.21 29.65,46.99 29.65,36.26 21.65,36.26 21.65,41.66 21.56,41.88 21.34,41.97 10.29,41.97 10.06,41.88 9.97,41.66 9.97,28 7.75,28 7.52,27.91 7.43,27.69 7.43,13.97 7.52,13.75 7.75,13.65 20.7,13.65 20.73,13.65 20.76,13.66 20.8,13.65 20.83,13.65 24.57,13.65 24.57,1.27 1.27,1.27 1.27,46.67 23.62,46.67 23.85,46.77 23.94,46.99 23.94,52.9 38.29,52.9 38.29,50.42 38.38,50.19 38.61,50.1 40.96,50.1 40.96,49.28 41.05,49.05 41.27,48.96 47.62,48.96 47.85,49.05 47.94,49.28 47.94,53.72 47.85,53.95 47.62,54.04 46.86,54.04 ; 1 cut-out
AD243X_VOUT2 on TOP: 51.37,54.8 51.18,54.99 49.66,54.99 48.77,54.1 48.77,53.72 48.89,53.59 49.66,53.59 49.91,53.85 51.67,53.85 51.86,53.66 54.55,53.66 54.6,53.71 54.6,55.7 53.86,55.7 53.86,55.06 53.6,54.8
AD243X_VOUT2 on TOP: 53.86,55.7 55.43,55.7 55.75,55.37 55.75,53.98 55.44,53.66 54.04,53.66 53.86,53.84
AD243X_VOUT2 on L3_PWR: 71.82,77.15 79.06,77.15 79.06,75.18 79.15,74.96 79.38,74.87 87.63,74.87 87.63,45.53 57.09,45.53 57.09,49.28 56.99,49.5 56.77,49.59 47.94,49.59 47.94,53.72 47.85,53.95 47.62,54.04 46.86,54.04 46.86,55.75 46.77,55.98 46.55,56.07 42.48,56.07 42.26,55.98 42.16,55.75 42.16,54.8 41.27,54.8 41.05,54.71 40.96,54.48 40.96,49.59 32.83,49.59 32.71,49.57 32.6,49.5 31.97,48.87 31.9,48.76 31.88,48.64 31.88,44.14 28.89,41.15 10.16,41.15 9.94,41.06 9.84,40.83 9.84,26.92 7.3,26.92 7.08,26.83 6.99,26.61 6.99,13.84 7.08,13.62 7.3,13.53 9.33,13.53 9.56,13.62 9.65,13.84 9.65,15.18 12.89,15.18 12.89,1.27 1.27,1.27 1.27,46.48 28.38,46.48 28.61,46.57 28.7,46.8 28.7,52.19 32.14,55.63 37.08,55.63 37.31,55.72 37.4,55.94 37.4,58.17 61.02,58.17 61.02,51.82 61.12,51.59 61.34,51.5 66.42,51.5 66.65,51.59 66.74,51.82 66.74,63.69 67.18,63.69 67.41,63.78 67.5,64.01 67.5,74.74 71.5,74.74 71.73,74.83 71.82,75.06 ; 1 cut-out
UNNAMED_2_AD243XW_I5_PLVDD on BOTTOM: 47.68,61.46 47.68,60.72 50.53,60.72 52.2,59.05 52.2,55.88 51.82,55.5 51.18,55.5 50.72,55.04 50.72,54.31 52.63,54.31 53.1,54.78 54.15,54.78 55.24,55.88 55.24,59.82 53.59,61.47 47.69,61.47
UNNAMED_2_AD243XW_I5_TRXVDD on TOP: 45.34,44.43 45.47,44.83 45.38,45.32 45.38,45.68 45.02,46.04 45.02,47.46 44.85,47.63 44.85,49.01 44.55,49.01 44.55,47.63 44.39,47.47 44.39,46.04 43.93,45.59 43.93,45.07 43.81,44.83 44,44.43 44,43.63 44.2,43.43 45.21,43.43 45.34,43.56
UNNAMED_2_AD243XW_I5_TRXVDD on BOTTOM: 45.34,44.43 45.47,44.83 45.38,45.32 45.38,45.68 45.02,46.04 44.39,46.04 43.93,45.59 43.93,45.07 43.81,44.83 44,44.43 44,43.63 44.2,43.43 45.21,43.43 45.34,43.56
UNNAMED_2_AD243XW_I5_TRXVDD on L4_PWR: 53.78,54.17 58.36,54.17 58.36,36.89 44.89,36.89 44.89,41.91 44.8,42.13 44.58,42.23 42.99,42.23 42.99,45.66 45.53,45.66 45.53,44.32 45.62,44.1 45.85,44.01 53.47,44.01 53.69,44.1 53.78,44.32 ; 1 cut-out
UNNAMED_5_ADLT3502_I61_BD on TOP: 13.63,53.73 12.54,53.73 12.54,53.31 11.61,52.37 10.16,52.37 9.82,52.72 8.68,52.72 8.68,51.54 7.24,50.1 7.24,48.7 12.08,48.7 12.54,48.25 13.63,48.25
UNNAMED_5_ADLT3502_I61_DA on TOP: 15.12,46.95 15.12,44.46 14.2,43.53 14.2,42.68 14.45,42.68 14.45,43.17 15.1,43.81 16,43.81 16.32,44.13 16.32,46.95
UNNAMED_5_ADLT3502_I61_SW on TOP: 13.55,42.68 13.55,43.35 13.19,43.7 13.19,45.44 13.51,45.76 13.51,46.95 12.03,46.95 10.78,45.7 7.24,45.7 7.24,44.31 11.06,44.31 12.69,42.68
UNNAMED_5_CAP_I36_N2 on TOP: 14.79,22.25 17.89,22.25 18.2,22.56 20.26,22.56 20.26,24.04 19.8,24.5 19.8,27.37 19.85,27.42 19.85,28.41 17.14,28.41 17,28.55 14.79,28.55
UNNAMED_5_CAP_I38_N2 on TOP: 19.8,32.65 18.66,32.65 18.66,31.99 17.35,30.69 15.53,30.69 15.53,29.5 18.11,29.5 18.61,28.99 19.85,28.99 19.85,32.6
UNNAMED_15_DIOSCHOTTKY_I87_P on BOTTOM: 29.87,11.58 29.87,12.8 32.03,12.8 32.33,12.5 32.33,8.66 31.37,8.66 31.37,10.08
UNNAMED_16_CAP_I25_N1 on BOTTOM: 65.61,19.3 65.61,21 68.76,21 69.08,20.68 70.85,20.68 70.87,20.7 72.14,20.7 72.14,18.92 71.5,18.29 69.22,18.29 68.58,17.65 68.58,13.08 69.06,12.6 69.06,7.72 68.55,7.21 60.1,7.21 59.18,8.13 59.18,9.91 59.69,10.41 60.58,10.41 61.09,9.91 61.09,9.27 61.72,8.64 64.39,8.64 64.9,9.14 64.9,11.56 65.15,11.81 65.79,11.81 66.17,12.19 66.17,14.39 65.7,14.86 65.7,16.09 65.3,16.48 63.54,16.48 63.54,17.68 64.67,17.68 65.41,18.41 65.41,19.1
UNNAMED_16_CAP_I25_N1 on L3_PWR: 60.64,18.61 67.63,18.61 67.63,6.79 59.44,6.79 59.21,6.7 59.12,6.48 59.12,4.89 52.26,4.89 52.26,9.21 60.32,9.21 60.55,9.3 60.64,9.53
UNNAMED_16_DIOSCHOTTKY_I60_P on BOTTOM: 61.98,16.48 60.23,16.48 60.23,17.94 60.5,18.21 60.5,19.29 61.98,19.29
UNNAMED_16_RES_I51_N2 on BOTTOM: 61.98,20 62.03,20.05 62.03,20.71 59.37,20.71 59.37,18.55 60.14,18.55 60.14,19.69 60.45,20
UNNAMED_17_CAP_I107_N1 on L3_PWR: 71.82,85.53 87.44,85.53 87.44,75.5 79.69,75.5 79.69,77.47 79.6,77.69 79.38,77.79 71.82,77.79
UNNAMED_17_CAP_I108_N1 on TOP: 64.43,38.9 64.43,40.6 64.14,40.89 62.1,40.89 61.85,40.64 61.85,38.86 62.1,38.61 64.14,38.61
UNNAMED_17_CAP_I108_N1 on L4_PWR: 58.99,48.13 65.98,48.13 65.98,36.13 63.63,36.13 63.4,36.04 63.31,35.81 63.31,31.94 56.26,31.94 56.04,31.85 55.94,31.62 55.94,26.48 37.91,26.48 37.91,35.94 37.82,36.17 37.59,36.26 30.29,36.26 30.29,46.67 32.7,46.67 32.7,44.2 32.8,43.97 33.02,43.88 42.35,43.88 42.35,41.91 42.45,41.69 42.67,41.59 44.26,41.59 44.26,36.58 44.35,36.35 44.58,36.26 58.67,36.26 58.9,36.35 58.99,36.58
UNNAMED_18_ADAU1701_I166_DVDD on TOP: 54.61,81.57 54.61,83.69 54.74,83.82 55.5,83.82 55.63,83.69 55.63,81.57
UNNAMED_18_ADAU1701_I166_DVDD on TOP: 54.62,75.6 51.09,75.6 50.93,75.44 50.93,74.17 51.09,74 54.62,74
UNNAMED_18_ADAU1701_I166_DVDD on L4_PWR: 47.31,86.17 56.45,86.17 56.45,83.12 50.16,83.12 49.94,83.03 49.85,82.8 49.85,79.76 49.94,79.53 50.16,79.44 54.17,79.44 54.17,73.6 47.31,73.6
UNNAMED_19_CAP_I17_N1 on TOP: 63.4,110.73 60.72,110.73 60.52,110.93 58.99,110.93 58.24,111.68 55.88,111.68 55.88,109.6 57.54,107.94 63.4,107.94
UNNAMED_19_CAP_I20_N1 on TOP: 58.52,118.22 56.12,118.22 54.61,116.71 54.61,116.14 53.43,116.14 53.43,118.08 54.95,119.59 58.67,119.59 58.97,119.89 63.4,119.89 63.4,117.09 61.37,117.09 61.17,117.29 59.45,117.29
UNNAMED_19_CAP_I26_N2 on TOP: 42.52,107.94 42.52,111.48 42.8,111.76 48.58,111.76 48.65,111.68 48.65,110.38 48.39,110.11 45.59,110.11 44.55,109.06 44.55,107.94
UNNAMED_19_CAP_I28_N1 on TOP: 46.85,118.28 48.47,118.28 50.04,116.71 50.04,116.14 51.21,116.14 51.21,118.08 49.87,119.42 46.85,119.42
UNNAMED_19_CAP_I28_N2 on TOP: 48.65,116.42 46.85,116.42 46.6,116.17 45,116.17 44.55,116.62 44.55,120.27 42.04,120.27 42.04,115.57 42.33,115.28 48.65,115.28
UNNAMED_19_CAP_I32_N2 on TOP: 73.09,94.83 67.35,100.57 68.27,103.69 70.74,105.81 70.74,106.92 70.1,107.56 68.71,107.56 68.71,111.5 72.9,111.5 73.74,110.66 73.74,107.52 75.44,105.81 77.91,103.69 78.83,100.57
UNNAMED_19_CAP_I33_N1 on TOP: 73.09,133 67.35,127.25 68.27,124.13 70.74,122.01 70.74,120.9 70.1,120.27 68.71,120.27 68.71,116.33 72.9,116.33 73.74,117.17 73.74,120.31 75.44,122.01 77.91,124.13 78.83,127.25
UNNAMED_19_CAP_I38_N2 on TOP: 32.83,133 38.57,127.25 37.65,124.13 35.18,122.01 35.18,120.9 35.81,120.27 37.21,120.27 37.21,116.33 33.02,116.33 32.18,117.17 32.18,120.31 30.48,122.01 28.01,124.13 27.09,127.25
UNNAMED_19_CAP_I44_N1 on TOP: 32.83,94.83 38.57,100.57 37.65,103.69 35.18,105.81 35.18,106.92 35.81,107.56 37.21,107.56 37.21,111.5 33.02,111.5 32.18,110.66 32.18,107.52 30.48,105.81 28.01,103.69 27.09,100.57

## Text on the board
Ref Des/Silkscreen Bottom: C | A
User.Comments: SEE NOTE 6 | (4 PLACES) | 5.    U7 IS A DEVICE-SOCKET COMBO AND FOLLOWS THIS SOLDERPASTE INSTRUCTION: | 6.    BOARD ASSEMBLY SPECIAL NOTES: | 7.    BOARDS TO BE SHIPPED SINGULATED AFTER ASSEMBLY PROCCESS. | (IN ORDER TO MINIMIZE MIC DEVICES (U1, U3, U4, U5) DAMAGE): | SMOOTHEN EDGES AND FREE FROM BURS AFTER DEPANELIZATION PROCESS. | A. DO NOT BOARD WASH OR CLEAN AFTER THE REFLOW PROCESS. | C. DO NOT DIRECTLY EXPOSE TO ULTRASONIC PROCESSING, WELDING, OR CLEANING. | E. DO NOT APPLY OVER 30 PSI OF AIR PRESSURE INTO THE PORT HOLE. | B. DO NOT BRUSH BOARD WITH OR WITHOUT SOLVENTS AFTER THE REFLOW PROCESS. | D. DO NOT INSERT ANY OBJECT IN PORT HOLE OF DEVICE AT ANY TIME. | F. DO NOT PULL A VACUUM OVER PORT HOLE OF THE MICROPHONE. | G. DO NOT APPLY A VACUUM WHEN REPACKING INTO SEALED BAGS AT A RATE | SUPPLIED PART | U7(DEVICE) | U7(SOCKET) | FASTER THAN 0.5 ATM/SEC. | INSTALLED SOCKET | INSTALLED PART | INSTALLED DUT | NO PASTEMASK | PASTEMASK
Ref Des/Assembly Top: C | A | MATE ENTRY
Ref Des/Silkscreen Top: VIN | TRXVDD | PLVDD | VOUT2 | BCLK | SYNC | DGND | DVDD | STEREO | AUDIO IN | IN 1 | OUT 1 | AUDIO OUT 1 | VDD_5V | GND | 3V3 | C | SHIELD | A | PDM | MIC | I2S | ADR2 | ADR1 | MUTE | PORT A | IRQ | CLK | SPI | SPKR L- | SPKR L | MAX LOAD: | 8 OHMS | TOWARDS MAIN | PORT B | EVAL-AD2437B1MZ | BUS-POWERED SUB-NODE | MULTI-PURPOSE | PINS | TOWARDS SUB | SCK | DRX1 | MISO | WP | SDA | SCL | BOOT | DISABLE | GREEN | 24V | LED FUNCTIONS | YELLOW | 5V | SPKR _R | SPKR_R- | SIGMA STUDIO | DRX0 | MP2 | DTX0 | MP3 | MP6 | ERROR | MCLK | MP7 | CS | MP8 | MP9 | DTX1 | RESET | SIO2 | +
DIMENSION: SEE DETAIL W | - | " " | (REF) | SEE DETAIL A | +2/-0 | DIA MAX
PAGE_OUTLINE: B | C | CHANGES AS PER ECR-109842 | CHANGES AS PER ECR-115080 | 24OCT22 | 10AUG23 | R. WHITNEY | CUSTOMER EVALUATION Z
User.11: 1 | A | C | SEE DETAIL X | (4 PLACES)
User.12: C | A
User.15: 15.    BOARDS TO BE SHIPPED IN ARRAY AND KEEP INTACT. | PANEL TO BE SUBJECTED TO CUSTOMER'S APPROVAL. | PANELED SOLDER PASTE STENCIL SHOULD BE SENT TO THE CUSTOMER. | 32 MILS 370HR | 5 MILS 370HR | NOTE: ALL IMPEDANCE TOLERANCE +/-10% | LAYER | L1 | L3 | L6 | 100 OHMS DP | 50 OHMS SE | IMPEDANCE | SE = SINGLE ENDED | DP = DIFFERENTIAL PAIR | REFERENCE | L5 | L2 | LINE WIDTH | 9.5 MILS | 7 MILS | 6.5 MILS | SPACE | N/A | IMPEDANCE TABLE
User.24: 08-      -07 | L2 GND
User.25: 08-      -08 | L3 PWR
User.26: 08-      -09 | L4 PWR
User.27: 08-      -10 | L5 GND
User.45: FIGURE | SIZE | 10.0 | 35.0 | 40.0 | 43.0 | 45.0 | 250.0 | 16.0 | 33.0 | 67.0 | 71.0 | 125.0 | 79.0x31.0 | PLATED | NON-PLATED | DRILL CHART: TOP to BOTTOM | ALL UNITS ARE IN MILS | QTY | 1340 | 16 | 10 | 8 | 71 | 4 | 2 | TOLERANCE/NOTES
